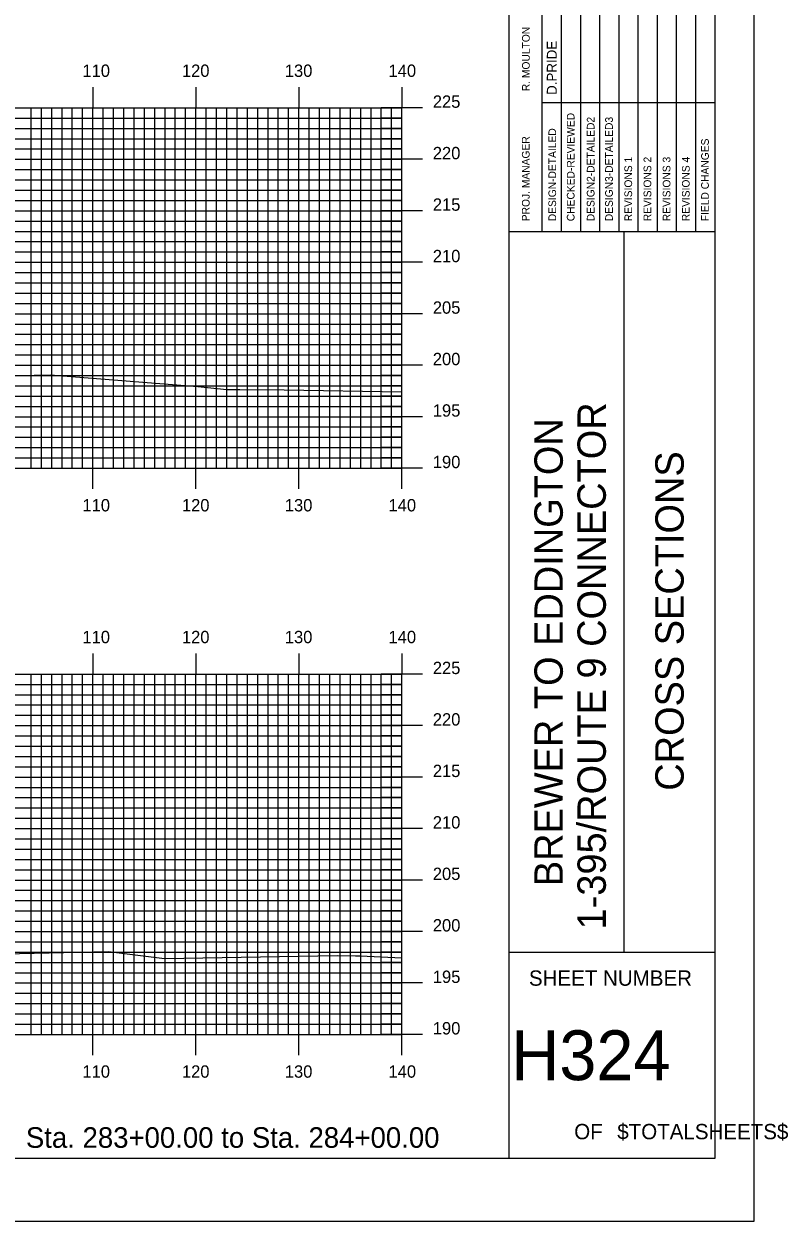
# Model space of a CAD drawing. Extents: x 1811767 to 1812110, y 442591 to 442811.
# Drawn here: x 1812036.2 to 1812110.4, y 442590.5 to 442706.8 of the extents above; entities that cross this region are included whole.
import ezdxf

# ---------------------------------------------------------------- set-up
doc = ezdxf.new("R2010")
doc.units = 0
for name, color, linetype in [('BORDER', 7, 'Continuous'), ('H_V ANNOTATION', 7, 'Continuous'), ('MAJOR', 7, 'Continuous'), ('MINOR', 7, 'Continuous'), ('PLOT BOUNDARY', 7, 'Continuous'), ('S_Roadway_Centerline', 7, 'Continuous')]:
    doc.layers.add(name, color=color, linetype=linetype)

msp = doc.modelspace()

# ---------------------------------------------------------------- linework, layer by layer
at = {"layer": 'BORDER'}
for p, q in [((1812083.32, 442596.67), (1812083.32, 442806.67)), ((1812083.32, 442686.67), (1812103.32, 442686.67)), ((1812094.5, 442616.67), (1812094.5, 442686.67)), ((1812083.32, 442616.67), (1812103.32, 442616.67))]:
    msp.add_line(p, q, dxfattribs=at)
msp.add_lwpolyline([(1811783.32, 442596.67), (1812103.32, 442596.67), (1812103.32, 442806.67), (1811783.32, 442806.67)], close=True, dxfattribs=at)
for points in [[(1812088.41, 442686.68), (1812088.41, 442721.67)], [(1812090.27, 442721.67), (1812090.27, 442686.68)], [(1812092.14, 442686.68), (1812092.14, 442721.67)], [(1812094, 442686.68), (1812094, 442721.67)], [(1812095.86, 442686.68), (1812095.86, 442721.67)], [(1812097.73, 442686.68), (1812097.73, 442721.67)], [(1812099.59, 442686.68), (1812099.59, 442721.67)], [(1812101.45, 442686.68), (1812101.45, 442721.67)], [(1812086.55, 442686.68), (1812086.55, 442720.26)], [(1812086.55, 442699.17), (1812103.32, 442699.17)]]:
    msp.add_lwpolyline(points, dxfattribs=at)
at = {"layer": 'MAJOR'}
for p, q in [((1812042.92, 442700.67), (1812042.92, 442698.67)), ((1812052.92, 442700.67), (1812052.92, 442698.67)), ((1812062.92, 442700.67), (1812062.92, 442698.67)), ((1812072.92, 442700.67), (1812072.92, 442698.67)), ((1811792.92, 442698.67), (1812072.92, 442698.67)), ((1811792.92, 442698.67), (1812072.92, 442698.67)), ((1812042.92, 442663.67), (1812042.92, 442698.67)), ((1812052.92, 442663.67), (1812052.92, 442698.67)), ((1812062.92, 442663.67), (1812062.92, 442698.67)), ((1812074.92, 442698.67), (1812070.91, 442698.67)), ((1812072.92, 442663.67), (1812072.92, 442698.67)), ((1812072.92, 442663.67), (1812072.92, 442698.67)), ((1811792.92, 442693.67), (1812072.92, 442693.67)), ((1812074.92, 442693.67), (1812070.91, 442693.67)), ((1811792.92, 442688.67), (1812072.92, 442688.67)), ((1812074.92, 442688.67), (1812070.91, 442688.67)), ((1811792.92, 442683.67), (1812072.92, 442683.67)), ((1812074.92, 442683.67), (1812070.91, 442683.67)), ((1811792.92, 442678.67), (1812072.92, 442678.67)), ((1812074.92, 442678.67), (1812070.91, 442678.67)), ((1811792.92, 442673.67), (1812072.92, 442673.67)), ((1812074.92, 442673.67), (1812070.91, 442673.67)), ((1811792.92, 442668.67), (1812072.92, 442668.67)), ((1812074.92, 442668.67), (1812070.91, 442668.67)), ((1811792.92, 442663.67), (1812072.92, 442663.67)), ((1811792.92, 442663.67), (1812072.92, 442663.67)), ((1812042.92, 442661.66), (1812042.92, 442663.67)), ((1812052.92, 442661.66), (1812052.92, 442663.67)), ((1812062.92, 442661.66), (1812062.92, 442663.67)), ((1812074.92, 442663.67), (1812070.91, 442663.67)), ((1812072.92, 442661.66), (1812072.92, 442663.67)), ((1812042.92, 442645.67), (1812042.92, 442643.67)), ((1812052.92, 442645.67), (1812052.92, 442643.67)), ((1812062.92, 442645.67), (1812062.92, 442643.67)), ((1812072.92, 442645.67), (1812072.92, 442643.67)), ((1811792.92, 442643.67), (1812072.92, 442643.67)), ((1811792.92, 442643.67), (1812072.92, 442643.67)), ((1812042.92, 442608.67), (1812042.92, 442643.67)), ((1812052.92, 442608.67), (1812052.92, 442643.67)), ((1812062.92, 442608.67), (1812062.92, 442643.67)), ((1812074.92, 442643.67), (1812070.91, 442643.67)), ((1812072.92, 442608.67), (1812072.92, 442643.67)), ((1812072.92, 442608.67), (1812072.92, 442643.67)), ((1811792.92, 442638.67), (1812072.92, 442638.67)), ((1812074.92, 442638.67), (1812070.91, 442638.67)), ((1811792.92, 442633.67), (1812072.92, 442633.67)), ((1812074.92, 442633.67), (1812070.91, 442633.67)), ((1811792.92, 442628.67), (1812072.92, 442628.67)), ((1812074.92, 442628.67), (1812070.91, 442628.67)), ((1811792.92, 442623.67), (1812072.92, 442623.67)), ((1812074.92, 442623.67), (1812070.91, 442623.67)), ((1811792.92, 442618.67), (1812072.92, 442618.67)), ((1812074.92, 442618.67), (1812070.91, 442618.67)), ((1811792.92, 442613.67), (1812072.92, 442613.67)), ((1812074.92, 442613.67), (1812070.91, 442613.67)), ((1811792.92, 442608.67), (1812072.92, 442608.67)), ((1811792.92, 442608.67), (1812072.92, 442608.67)), ((1812042.92, 442606.66), (1812042.92, 442608.67)), ((1812052.92, 442606.66), (1812052.92, 442608.67)), ((1812062.92, 442606.66), (1812062.92, 442608.67)), ((1812074.92, 442608.67), (1812070.91, 442608.67)), ((1812072.92, 442606.66), (1812072.92, 442608.67))]:
    msp.add_line(p, q, dxfattribs=at)
at = {"layer": 'MINOR'}
for p, q in [((1812036.92, 442663.67), (1812036.92, 442698.67)), ((1812037.92, 442663.67), (1812037.92, 442698.67)), ((1812038.92, 442663.67), (1812038.92, 442698.67)), ((1812039.92, 442663.67), (1812039.92, 442698.67)), ((1812040.92, 442663.67), (1812040.92, 442698.67)), ((1812041.92, 442663.67), (1812041.92, 442698.67)), ((1812043.92, 442663.67), (1812043.92, 442698.67)), ((1812044.92, 442663.67), (1812044.92, 442698.67)), ((1812045.92, 442663.67), (1812045.92, 442698.67)), ((1812046.92, 442663.67), (1812046.92, 442698.67)), ((1812047.92, 442663.67), (1812047.92, 442698.67)), ((1812048.92, 442663.67), (1812048.92, 442698.67)), ((1812049.92, 442663.67), (1812049.92, 442698.67)), ((1812050.92, 442663.67), (1812050.92, 442698.67)), ((1812051.92, 442663.67), (1812051.92, 442698.67)), ((1812053.92, 442663.67), (1812053.92, 442698.67)), ((1812054.92, 442663.67), (1812054.92, 442698.67)), ((1812055.92, 442663.67), (1812055.92, 442698.67)), ((1812056.92, 442663.67), (1812056.92, 442698.67)), ((1812057.92, 442663.67), (1812057.92, 442698.67)), ((1812058.92, 442663.67), (1812058.92, 442698.67)), ((1812059.92, 442663.67), (1812059.92, 442698.67)), ((1812060.92, 442663.67), (1812060.92, 442698.67)), ((1812061.92, 442663.67), (1812061.92, 442698.67)), ((1812063.92, 442663.67), (1812063.92, 442698.67)), ((1812064.92, 442663.67), (1812064.92, 442698.67)), ((1812065.92, 442663.67), (1812065.92, 442698.67)), ((1812066.92, 442663.67), (1812066.92, 442698.67)), ((1812067.92, 442663.67), (1812067.92, 442698.67)), ((1812068.92, 442663.67), (1812068.92, 442698.67)), ((1812069.92, 442663.67), (1812069.92, 442698.67)), ((1812070.92, 442663.67), (1812070.92, 442698.67)), ((1812071.92, 442663.67), (1812071.92, 442698.67)), ((1811792.92, 442697.67), (1812072.92, 442697.67)), ((1812072.92, 442697.67), (1812070.91, 442697.67)), ((1811792.92, 442696.67), (1812072.92, 442696.67)), ((1812072.92, 442696.67), (1812070.91, 442696.67)), ((1811792.92, 442695.67), (1812072.92, 442695.67)), ((1812072.92, 442695.67), (1812070.91, 442695.67)), ((1811792.92, 442694.67), (1812072.92, 442694.67)), ((1812072.92, 442694.67), (1812070.91, 442694.67)), ((1811792.92, 442692.67), (1812072.92, 442692.67)), ((1811792.92, 442691.67), (1812072.92, 442691.67)), ((1812072.92, 442692.67), (1812070.91, 442692.67)), ((1812072.92, 442691.67), (1812070.91, 442691.67)), ((1811792.92, 442690.67), (1812072.92, 442690.67)), ((1812072.92, 442690.67), (1812070.91, 442690.67)), ((1811792.92, 442689.67), (1812072.92, 442689.67)), ((1812072.92, 442689.67), (1812070.91, 442689.67)), ((1811792.92, 442687.67), (1812072.92, 442687.67)), ((1812072.92, 442687.67), (1812070.91, 442687.67)), ((1811792.92, 442686.67), (1812072.92, 442686.67)), ((1812072.92, 442686.67), (1812070.91, 442686.67)), ((1811792.92, 442685.67), (1812072.92, 442685.67)), ((1811792.92, 442684.67), (1812072.92, 442684.67)), ((1812072.92, 442685.67), (1812070.91, 442685.67)), ((1812072.92, 442684.67), (1812070.91, 442684.67)), ((1811792.92, 442682.67), (1812072.92, 442682.67)), ((1812072.92, 442682.67), (1812070.91, 442682.67)), ((1811792.92, 442681.67), (1812072.92, 442681.67)), ((1812072.92, 442681.67), (1812070.91, 442681.67)), ((1811792.92, 442680.67), (1812072.92, 442680.67)), ((1812072.92, 442680.67), (1812070.91, 442680.67)), ((1811792.92, 442679.67), (1812072.92, 442679.67)), ((1812072.92, 442679.67), (1812070.91, 442679.67)), ((1811792.92, 442677.67), (1812072.92, 442677.67)), ((1811792.92, 442676.67), (1812072.92, 442676.67)), ((1812072.92, 442677.67), (1812070.91, 442677.67)), ((1812072.92, 442676.67), (1812070.91, 442676.67)), ((1811792.92, 442675.67), (1812072.92, 442675.67)), ((1812072.92, 442675.67), (1812070.91, 442675.67)), ((1811792.92, 442674.67), (1812072.92, 442674.67)), ((1812072.92, 442674.67), (1812070.91, 442674.67)), ((1811792.92, 442672.67), (1812072.92, 442672.67)), ((1812072.92, 442672.67), (1812070.91, 442672.67)), ((1811792.92, 442671.67), (1812072.92, 442671.67)), ((1812072.92, 442671.67), (1812070.91, 442671.67)), ((1811792.92, 442670.67), (1812072.92, 442670.67)), ((1811792.92, 442669.67), (1812072.92, 442669.67)), ((1812072.92, 442670.67), (1812070.91, 442670.67)), ((1812072.92, 442669.67), (1812070.91, 442669.67)), ((1811792.92, 442667.67), (1812072.92, 442667.67)), ((1812072.92, 442667.67), (1812070.91, 442667.67)), ((1811792.92, 442666.67), (1812072.92, 442666.67)), ((1812072.92, 442666.67), (1812070.91, 442666.67)), ((1811792.92, 442665.67), (1812072.92, 442665.67)), ((1812072.92, 442665.67), (1812070.91, 442665.67)), ((1811792.92, 442664.67), (1812072.92, 442664.67)), ((1812072.92, 442664.67), (1812070.91, 442664.67)), ((1812036.92, 442608.67), (1812036.92, 442643.67)), ((1812037.92, 442608.67), (1812037.92, 442643.67)), ((1812038.92, 442608.67), (1812038.92, 442643.67)), ((1812039.92, 442608.67), (1812039.92, 442643.67)), ((1812040.92, 442608.67), (1812040.92, 442643.67)), ((1812041.92, 442608.67), (1812041.92, 442643.67)), ((1812043.92, 442608.67), (1812043.92, 442643.67)), ((1812044.92, 442608.67), (1812044.92, 442643.67)), ((1812045.92, 442608.67), (1812045.92, 442643.67)), ((1812046.92, 442608.67), (1812046.92, 442643.67)), ((1812047.92, 442608.67), (1812047.92, 442643.67)), ((1812048.92, 442608.67), (1812048.92, 442643.67)), ((1812049.92, 442608.67), (1812049.92, 442643.67)), ((1812050.92, 442608.67), (1812050.92, 442643.67)), ((1812051.92, 442608.67), (1812051.92, 442643.67)), ((1812053.92, 442608.67), (1812053.92, 442643.67)), ((1812054.92, 442608.67), (1812054.92, 442643.67)), ((1812055.92, 442608.67), (1812055.92, 442643.67)), ((1812056.92, 442608.67), (1812056.92, 442643.67)), ((1812057.92, 442608.67), (1812057.92, 442643.67)), ((1812058.92, 442608.67), (1812058.92, 442643.67)), ((1812059.92, 442608.67), (1812059.92, 442643.67)), ((1812060.92, 442608.67), (1812060.92, 442643.67)), ((1812061.92, 442608.67), (1812061.92, 442643.67)), ((1812063.92, 442608.67), (1812063.92, 442643.67)), ((1812064.92, 442608.67), (1812064.92, 442643.67)), ((1812065.92, 442608.67), (1812065.92, 442643.67)), ((1812066.92, 442608.67), (1812066.92, 442643.67)), ((1812067.92, 442608.67), (1812067.92, 442643.67)), ((1812068.92, 442608.67), (1812068.92, 442643.67)), ((1812069.92, 442608.67), (1812069.92, 442643.67)), ((1812070.92, 442608.67), (1812070.92, 442643.67)), ((1812071.92, 442608.67), (1812071.92, 442643.67)), ((1811792.92, 442642.67), (1812072.92, 442642.67)), ((1811792.92, 442641.67), (1812072.92, 442641.67)), ((1812072.92, 442642.67), (1812070.91, 442642.67)), ((1812072.92, 442641.67), (1812070.91, 442641.67)), ((1811792.92, 442640.67), (1812072.92, 442640.67)), ((1812072.92, 442640.67), (1812070.91, 442640.67)), ((1811792.92, 442639.67), (1812072.92, 442639.67)), ((1812072.92, 442639.67), (1812070.91, 442639.67)), ((1811792.92, 442637.67), (1812072.92, 442637.67)), ((1812072.92, 442637.67), (1812070.91, 442637.67)), ((1811792.92, 442636.67), (1812072.92, 442636.67)), ((1812072.92, 442636.67), (1812070.91, 442636.67)), ((1811792.92, 442635.67), (1812072.92, 442635.67)), ((1811792.92, 442634.67), (1812072.92, 442634.67)), ((1812072.92, 442635.67), (1812070.91, 442635.67)), ((1812072.92, 442634.67), (1812070.91, 442634.67)), ((1811792.92, 442632.67), (1812072.92, 442632.67)), ((1812072.92, 442632.67), (1812070.91, 442632.67)), ((1811792.92, 442631.67), (1812072.92, 442631.67)), ((1812072.92, 442631.67), (1812070.91, 442631.67)), ((1811792.92, 442630.67), (1812072.92, 442630.67)), ((1812072.92, 442630.67), (1812070.91, 442630.67)), ((1811792.92, 442629.67), (1812072.92, 442629.67)), ((1812072.92, 442629.67), (1812070.91, 442629.67)), ((1811792.92, 442627.67), (1812072.92, 442627.67)), ((1811792.92, 442626.67), (1812072.92, 442626.67)), ((1812072.92, 442627.67), (1812070.91, 442627.67)), ((1812072.92, 442626.67), (1812070.91, 442626.67)), ((1811792.92, 442625.67), (1812072.92, 442625.67)), ((1812072.92, 442625.67), (1812070.91, 442625.67)), ((1811792.92, 442624.67), (1812072.92, 442624.67)), ((1812072.92, 442624.67), (1812070.91, 442624.67)), ((1811792.92, 442622.67), (1812072.92, 442622.67)), ((1812072.92, 442622.67), (1812070.91, 442622.67)), ((1811792.92, 442621.67), (1812072.92, 442621.67)), ((1812072.92, 442621.67), (1812070.91, 442621.67)), ((1811792.92, 442620.67), (1812072.92, 442620.67)), ((1811792.92, 442619.67), (1812072.92, 442619.67)), ((1812072.92, 442620.67), (1812070.91, 442620.67)), ((1812072.92, 442619.67), (1812070.91, 442619.67)), ((1811792.92, 442617.67), (1812072.92, 442617.67)), ((1812072.92, 442617.67), (1812070.91, 442617.67)), ((1811792.92, 442616.67), (1812072.92, 442616.67)), ((1812072.92, 442616.67), (1812070.91, 442616.67)), ((1811792.92, 442615.67), (1812072.92, 442615.67)), ((1812072.92, 442615.67), (1812070.91, 442615.67)), ((1811792.92, 442614.67), (1812072.92, 442614.67)), ((1812072.92, 442614.67), (1812070.91, 442614.67)), ((1811792.92, 442612.67), (1812072.92, 442612.67)), ((1812072.92, 442612.67), (1812070.91, 442612.67)), ((1811792.92, 442611.67), (1812072.92, 442611.67)), ((1812072.92, 442611.67), (1812070.91, 442611.67)), ((1811792.92, 442610.67), (1812072.92, 442610.67)), ((1812072.92, 442610.67), (1812070.91, 442610.67)), ((1811792.92, 442609.67), (1812072.92, 442609.67)), ((1812072.92, 442609.67), (1812070.91, 442609.67))]:
    msp.add_line(p, q, dxfattribs=at)
at = {"layer": 'PLOT BOUNDARY'}
msp.add_lwpolyline([(1811767.13, 442590.55), (1812107.13, 442590.55), (1812107.13, 442810.55), (1811767.13, 442810.55)], close=True, dxfattribs=at)
at = {"layer": 'S_Roadway_Centerline'}
for points in [[(1811979.59, 442672.39), (1811993.71, 442672.13), (1812001.57, 442672.31), (1812013.17, 442672.71), (1812017.34, 442672.89), (1812019.62, 442672.87), (1812031.04, 442672.58), (1812038.76, 442672.72), (1812053.11, 442671.61), (1812055.91, 442671.31), (1812057.19, 442671.32), (1812061.48, 442671.27), (1812072.92, 442671.09)], [(1811984.1, 442616.8), (1811994.98, 442617.07), (1811997.24, 442617.18), (1812001.07, 442617.12), (1812014.22, 442616.75), (1812021.38, 442616.44), (1812035.8, 442616.52), (1812044.42, 442616.73), (1812049.88, 442616.05), (1812066.64, 442616.35), (1812068.4, 442616.3), (1812068.88, 442616.31), (1812072.92, 442616.12)]]:
    msp.add_lwpolyline(points, dxfattribs=at)

# ---------------------------------------------------------------- texts
at = {"layer": 'BORDER'}
for s, height, p in [('R. MOULTON', 0.745, (1812085.33, 442700.28)), ('D.PRIDE', 0.969, (1812087.96, 442699.92)), ('CHECKED-REVIEWED', 0.7455, (1812089.68, 442687.65)), ('DESIGN2-DETAILED2', 0.7455, (1812091.62, 442687.65)), ('DESIGN3-DETAILED3', 0.7455, (1812093.4, 442687.65)), ('DESIGN-DETAILED', 0.7455, (1812087.89, 442687.65)), ('PROJ. MANAGER', 0.7455, (1812085.32, 442687.65)), ('FIELD CHANGES', 0.7455, (1812102.72, 442687.65)), ('REVISIONS 1', 0.7455, (1812095.27, 442687.65)), ('REVISIONS 2', 0.7455, (1812097.13, 442687.65)), ('REVISIONS 3', 0.7455, (1812098.99, 442687.65)), ('REVISIONS 4', 0.7455, (1812100.86, 442687.65)), ('1-395/ROUTE 9 CONNECTOR', 2.7557, (1812092.72, 442618.87)), ('BREWER TO EDDINGTON', 2.7557, (1812088.54, 442623.07)), ('CROSS SECTIONS', 2.7557, (1812100.28, 442632.34))]:
    msp.add_text(s, height=height, rotation=90, dxfattribs=at).set_placement(p)
for s, height, p in [('SHEET NUMBER', 1.4905, (1812085.25, 442613.4)), ('H324', 4.839, (1812083.53, 442604.23)), ('OF', 1.491, (1812089.65, 442598.49)), ('$TOTALSHEETS$', 1.4905, (1812093.83, 442598.49))]:
    msp.add_text(s, height=height, dxfattribs=at).set_placement(p)
at = {"layer": 'H_V ANNOTATION'}
for s, height, p in [('110', 1.2, (1812041.9, 442701.67)), ('120', 1.2, (1812051.56, 442701.67)), ('130', 1.2, (1812061.55, 442701.67)), ('140', 1.2, (1812071.62, 442701.67)), ('225', 1.2, (1812075.92, 442698.67)), ('220', 1.2, (1812075.92, 442693.67)), ('215', 1.2, (1812075.92, 442688.67)), ('210', 1.2, (1812075.92, 442683.67)), ('205', 1.2, (1812075.92, 442678.67)), ('200', 1.2, (1812075.92, 442673.67)), ('195', 1.2, (1812075.92, 442668.67)), ('190', 1.2, (1812075.92, 442663.67)), ('110', 1.2, (1812041.9, 442659.47)), ('120', 1.2, (1812051.56, 442659.47)), ('130', 1.2, (1812061.55, 442659.47)), ('140', 1.2, (1812071.62, 442659.47)), ('110', 1.2, (1812041.9, 442646.67)), ('120', 1.2, (1812051.56, 442646.67)), ('130', 1.2, (1812061.55, 442646.67)), ('140', 1.2, (1812071.62, 442646.67)), ('225', 1.2, (1812075.92, 442643.67)), ('220', 1.2, (1812075.92, 442638.67)), ('215', 1.2, (1812075.92, 442633.67)), ('210', 1.2, (1812075.92, 442628.67)), ('205', 1.2, (1812075.92, 442623.67)), ('200', 1.2, (1812075.92, 442618.67)), ('195', 1.2, (1812075.92, 442613.67)), ('190', 1.2, (1812075.92, 442608.67)), ('110', 1.2, (1812041.9, 442604.47)), ('120', 1.2, (1812051.56, 442604.47)), ('130', 1.2, (1812061.55, 442604.47)), ('140', 1.2, (1812071.62, 442604.47)), ('Sta. 283+00.00 to Sta. 284+00.00', 2.0004, (1812036.41, 442597.66))]:
    msp.add_text(s, height=height, dxfattribs=at).set_placement(p)

doc.saveas('drawing.dxf')
